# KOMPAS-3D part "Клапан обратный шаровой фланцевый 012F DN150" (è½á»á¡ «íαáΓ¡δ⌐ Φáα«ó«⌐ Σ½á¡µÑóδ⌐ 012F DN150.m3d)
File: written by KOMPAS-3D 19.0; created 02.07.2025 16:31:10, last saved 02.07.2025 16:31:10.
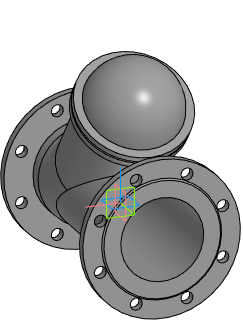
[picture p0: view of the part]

Document properties: Полное имя файла: E:\Dendor Работа Сачек\3D для проектировщиков\5.3 Тип 012F, 012F.Z Клапан обратный шаровой фланцевый\stp_Клапан обратный шаровой фланцевый 012F\Клапан обратный шаровой фланцевый 012F DN150.m3d

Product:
- Part/product: Клапан обратный шаровой фланцевый 012F DN150

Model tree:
1. Операция без истории:1  (labels: Клапан обратный шаровой фланцевый 012F DN150)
